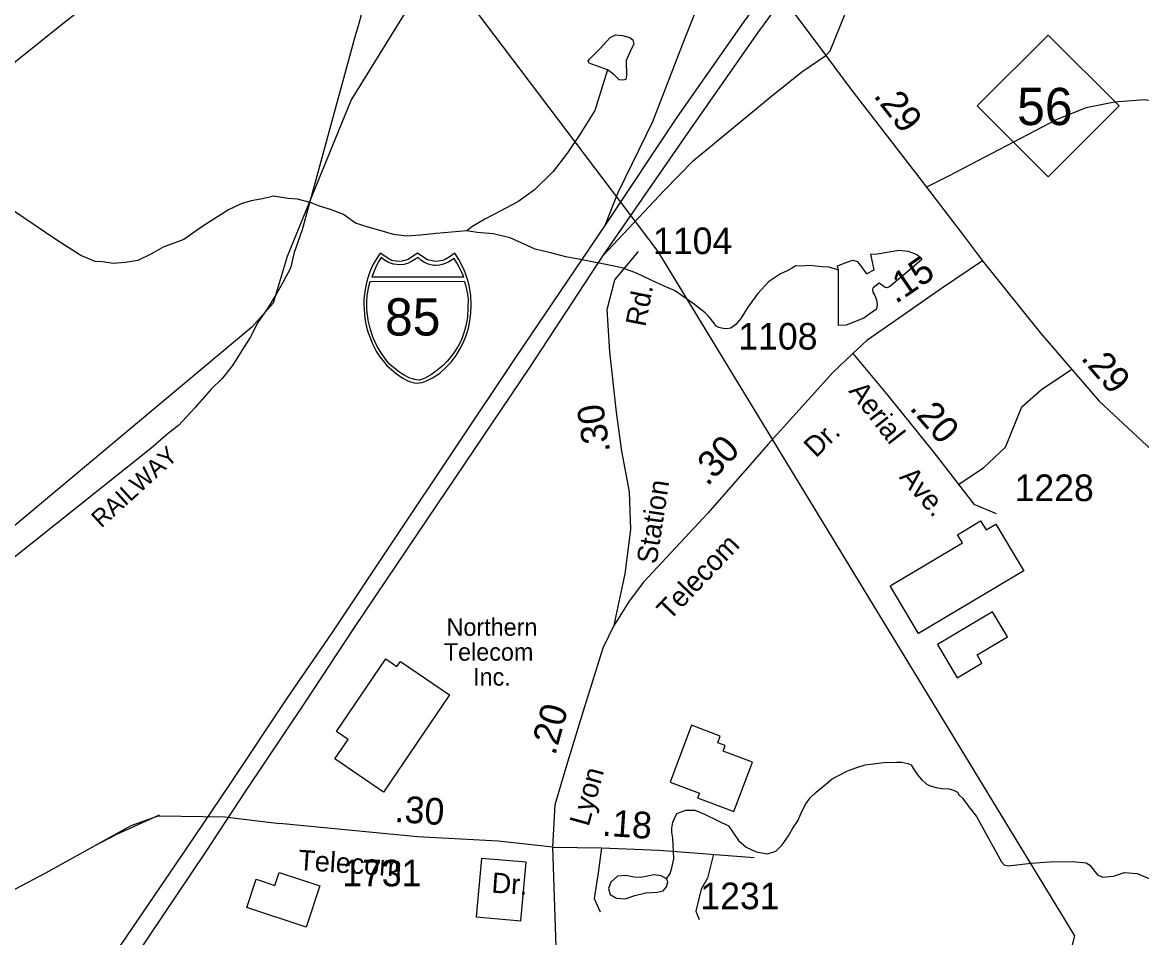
# Model space of a CAD drawing. Extents: x 2056842 to 2160602, y 826753 to 1016856.
# Drawn here: x 2077674 to 2082930, y 868296 to 872595 of the extents above; entities that cross this region are included whole.
import ezdxf

# ---------------------------------------------------------------- set-up
doc = ezdxf.new("R2010")
doc.units = 0
for name, color, linetype in [('Exist Boundary Land Use Reservation Military US Department of Defense', 7, 'Continuous'), ('Exist Cultural Manufacturing Building Label', 7, 'Continuous'), ('Exist Cultural Warehouse Building Footprint', 7, 'Continuous'), ('Exist Hydrographic Creek Single Shore', 7, 'Continuous'), ('Exist Hydrographic Misc Water Feature', 7, 'Continuous'), ('Exist Railroad Mainline', 7, 'Continuous'), ('Exist Railroad Mainline Label', 7, 'Continuous'), ('Exist Road Non-System Type 51', 7, 'Continuous'), ('Exist Road Primary Interstate Divided Center Attributed', 7, 'Continuous'), ('Exist Road Primary Interstate Ramp 1 Lane Attributed', 7, 'Continuous'), ('Exist Road Primary Interstate Shield CELL', 7, 'Continuous'), ('Exist Road Primary Interstate Shield Number Label', 7, 'Continuous'), ('Exist Road Primary NC Attributed', 7, 'Continuous'), ('Exist Road Primary NC Service Mileage Hundredths English Label', 7, 'Continuous'), ('Exist Road Primary NC Shield CELL', 7, 'Continuous'), ('Exist Road Primary NC Shield Number Label', 7, 'Continuous'), ('Exist Road Secondary Mileage Hundredths English Label', 7, 'Continuous'), ('Exist Road Secondary Type 51 Attributed', 7, 'Continuous'), ('Exist Road Secondary Type 51 Label', 7, 'Continuous'), ('Exist Road Secondary Type 51 Number Label', 7, 'Continuous'), ('Exist Utilities Electrical Transmission Line', 7, 'Continuous')]:
    doc.layers.add(name, color=color, linetype=linetype)

msp = doc.modelspace()

# ---------------------------------------------------------------- linework, layer by layer
at = {"layer": 'Exist Boundary Land Use Reservation Military US Department of Defense'}
msp.add_lwpolyline([(2079729.3, 873057.2), (2079217.9, 872231.6), (2078917.6, 871495.8), (2078852.5, 871275.5), (2078751.7, 871162.9), (2076995.4, 869694.7), (2075448.8, 868458.6), (2072205.6, 865914.9), (2069683.3, 863910.7), (2068119, 862645.9), (2067327.2, 862021.6)], dxfattribs=at)
at = {"layer": 'Exist Cultural Warehouse Building Footprint'}
for points in [[(2081749.5, 869947.8), (2082088.7, 870149.8), (2082065.6, 870188.5), (2082174.4, 870253.3), (2082199.7, 870210.8), (2082246.2, 870238.5), (2082369.5, 870031.6), (2082376.9, 870019.1), (2081882.5, 869724.6)], [(2082230, 869826.6), (2081971.6, 869673.1), (2082064.3, 869517), (2082180.4, 869586), (2082157.4, 869624.7), (2082299.7, 869709.2)], [(2079680.8, 869436), (2079369.9, 868979.5), (2079141.3, 869135.2), (2079204.1, 869227.4), (2079149.4, 869264.6), (2079381.3, 869605.1), (2079433.4, 869569.6), (2079449.6, 869593.4)], [(2080816.9, 869293.3), (2080716, 869026.7), (2080853.5, 868974.6), (2080845.1, 868952.5), (2081015.3, 868888), (2081103, 869119.8), (2080965.3, 869171.9), (2080975.3, 869198.5), (2080940.3, 869211.8), (2080951.8, 869242.2)], [(2079830.1, 868668.4), (2079805.9, 868393.7), (2080015.3, 868375.2), (2080039.5, 868649.9)], [(2079006.6, 868345.2), (2078728, 868438.1), (2078772, 868570.2), (2078859.2, 868541.1), (2078879.8, 868602.9), (2079071.2, 868539.1)]]:
    msp.add_lwpolyline(points, close=True, dxfattribs=at)
at = {"layer": 'Exist Hydrographic Creek Single Shore'}
msp.add_lwpolyline([(2079761.9, 871615.5), (2079617.9, 871603.3), (2079543.9, 871595), (2079479.9, 871590.9), (2079417.8, 871598.7), (2079370, 871612.4), (2079297.6, 871632.3), (2079238, 871651.9), (2079181.8, 871691.7), (2079121.7, 871715.9), (2079073.7, 871729.6), (2079025.7, 871749.5), (2078965.5, 871765.1), (2078921.6, 871766.9), (2078853.3, 871778.8), (2078801.6, 871766.4), (2078749.3, 871756.5), (2078701.6, 871742.2), (2078641.5, 871714), (2078590, 871682), (2078521.7, 871637.7), (2078431.9, 871575.3), (2078336.1, 871539.1), (2078280.4, 871507), (2078216.6, 871476.9), (2078156.7, 871466.5), (2078100.3, 871462.5), (2078052.4, 871470.2), (2078016.5, 871472), (2077948.6, 871500.2), (2077836.4, 871571.5), (2077574, 871748.9)], dxfattribs=at)
at = {"layer": 'Exist Hydrographic Misc Water Feature'}
for points in [[(2080422.4, 872371.3), (2080336.2, 872402.6), (2080331.2, 872412.6), (2080337.5, 872422.6), (2080386.2, 872470.1), (2080434.9, 872523.9), (2080459.9, 872536.4), (2080492.4, 872532.6), (2080527.4, 872523.9), (2080541.1, 872512.6), (2080546.1, 872493.9), (2080529.9, 872461.4), (2080509.9, 872415.1), (2080511.1, 872345.1), (2080507.4, 872326.3), (2080494.9, 872322.6), (2080476.1, 872325.1), (2080452.4, 872350.1), (2080422.4, 872371.3)], [(2080422.4, 872371.3), (2080362.3, 872181.4), (2080292.3, 872067.4), (2080234.5, 871981.3), (2080167.1, 871895), (2080079.3, 871808.9), (2080001.4, 871752.5), (2079917.5, 871708.4), (2079845.7, 871669.7), (2079785.7, 871633.9), (2079761.9, 871615.5)], [(2081506.3, 871431.4), (2081462.2, 871445), (2081430.2, 871447), (2081370.3, 871452.8), (2081334.4, 871450.5), (2081306.3, 871450.7), (2081290.5, 871442.6), (2081266.1, 871428.5), (2081234.4, 871414.1), (2081178.8, 871376.3), (2081128.5, 871321.9), (2081080.8, 871257.7), (2081048.8, 871203.8), (2081025, 871175.7), (2081001.2, 871157.8), (2080981.3, 871155.6), (2080965.5, 871157.5), (2080945, 871161.4), (2080933.1, 871167.3), (2080921, 871183.4), (2080897, 871215.3), (2080880.8, 871231.2), (2080824.9, 871275), (2080757, 871321.1), (2080736.7, 871335), (2080688.9, 871356.5), (2080626.4, 871384.6), (2080558.1, 871416.1), (2080490.2, 871442.2), (2080422.3, 871455.8), (2080302.4, 871479.7), (2080226.3, 871493.2), (2080160.1, 871510.9), (2080082.4, 871528.8), (2079964.3, 871582.4), (2079885.9, 871602), (2079809.9, 871607.8), (2079761.9, 871615.5)], [(2081506.3, 871431.4), (2081502.4, 871451.1), (2081538.2, 871465.5), (2081574.1, 871477.5), (2081594, 871471.7), (2081606.1, 871459.7), (2081638.3, 871413.8), (2081674.2, 871431.9), (2081658, 871505.8), (2081690.2, 871507.8), (2081790.3, 871524.3), (2081833.7, 871520.2), (2081858.1, 871510.3), (2081874.1, 871504.3), (2081889.9, 871492.6), (2081898.1, 871480.4), (2081862, 871450.4), (2081746.6, 871351.9), (2081734.5, 871348.1), (2081726.5, 871350.2), (2081714.6, 871358.1), (2081698.2, 871369.9), (2081670.3, 871347.7), (2081666.4, 871341.8), (2081668.7, 871327.6), (2081676.7, 871311.8), (2081684.9, 871291.9), (2081689, 871267.7), (2081684.6, 871247.7), (2081665, 871233.7), (2081625, 871205.6), (2081543.2, 871173.4), (2081507.1, 871171.2), (2081506.9, 871175.3), (2081506.3, 871431.4)], [(2080699.8, 868572.9), (2080716, 868597.9), (2080723.5, 868624.2), (2080733.5, 868666.7), (2080728.5, 868762.8), (2080724.8, 868791), (2080724.6, 868810.9), (2080728.5, 868839.2), (2080736.3, 868855), (2080748.4, 868879.2), (2080789.7, 868894.2), (2080832.2, 868894.2), (2080877.2, 868875.5), (2080942.2, 868845.5), (2080990.9, 868821.7), (2081037.1, 868751.7), (2081073.4, 868721.7), (2081119.6, 868699.2), (2081173.3, 868689.2), (2081213.3, 868702.9), (2081242.1, 868731.7), (2081272.7, 868774.5), (2081292.4, 868810.9), (2081316.4, 868844.9), (2081334.2, 868888.9), (2081353.9, 868924.9), (2081374.4, 868953.1), (2081402.1, 868979.3), (2081437.6, 869009.2), (2081477.8, 869041.3), (2081513.4, 869061.4), (2081545.4, 869077.7), (2081587.7, 869093.6), (2081631.7, 869108), (2081719.7, 869118.2), (2081779.6, 869120.4), (2081803.8, 869120.4), (2081831.7, 869114.6), (2081847.7, 869108.5), (2081859.6, 869088.4), (2081877.6, 869060.6), (2081897.7, 869036.9), (2081917.8, 869018.8), (2081937.7, 869008.9), (2081965.8, 869001), (2081994.1, 868997.1), (2082025.9, 868995), (2082049.6, 868987.5), (2082065.8, 868979.3), (2082074, 868965.4), (2082090, 868949.2), (2082118.1, 868911.3), (2082154.4, 868865.7), (2082206.6, 868770.6), (2082272.9, 868653), (2082285.4, 868638), (2082305.4, 868633), (2082344.1, 868638), (2082411.6, 868645.5), (2082497.8, 868653), (2082605.2, 868654.3), (2082670.2, 868648), (2082686.4, 868636.8), (2082722.7, 868590.4), (2082746.4, 868580.4), (2082798.9, 868585.4), (2082850.1, 868601.7), (2082910.1, 868596.7), (2083017.1, 868552.2)], [(2080699.8, 868572.9), (2080673.5, 868586.7), (2080639.8, 868591.7), (2080609.8, 868585.4), (2080576.1, 868577.9), (2080547.3, 868580.4), (2080508.6, 868587.9), (2080468.6, 868585.4), (2080437.4, 868556.7), (2080426.1, 868526.7), (2080434.9, 868499.1), (2080463.6, 868481.6), (2080504.9, 868479.1), (2080549.8, 868494.1), (2080602.3, 868506.7), (2080656, 868510.4), (2080683.5, 868516.7), (2080699.8, 868535.4), (2080704.8, 868557.9), (2080699.8, 868572.9)]]:
    msp.add_lwpolyline(points, dxfattribs=at)
at = {"layer": 'Exist Railroad Mainline'}
msp.add_lwpolyline([(2079275.5, 872670.7), (2079253.8, 872588.8), (2079234, 872520.8), (2078988.7, 871619.9), (2078951.1, 871513.9), (2078933.4, 871439.9), (2078897.6, 871373.8), (2078869.8, 871323.6), (2078825.9, 871251.5), (2078780.1, 871185.4), (2078744.3, 871115.3), (2078704.6, 871053.1), (2078660.7, 870983), (2078612.9, 870922.8), (2078561.3, 870872.7), (2078483.4, 870784.5), (2078407.7, 870702.2), (2078359.8, 870666), (2078278.1, 870593.9), (2077141.8, 869689)], dxfattribs=at)
at = {"layer": 'Exist Road Non-System Type 51'}
for points in [[(2083433.4, 872190.3), (2083365.9, 872183.6), (2083168.3, 872196.9), (2082946, 872231.1), (2082803.5, 872219.7), (2082670.5, 872193.1), (2082531.7, 872138), (2082023.4, 871872.7), (2081920.3, 871820.3)], [(2082069.9, 870425.1), (2082188.8, 870504), (2082291.4, 870599.1), (2082367.4, 870789.2), (2082460.5, 870871), (2082601.8, 870965.8)], [(2078012.9, 868726.8), (2078185.8, 868822.1), (2078312.4, 868868.3), (2078419.7, 868866.8), (2078625.5, 868863.2), (2078881.5, 868831.6)], [(2080393.1, 868718.5), (2080377.9, 868600.6), (2080358.9, 868480.8), (2080387.4, 868418.1)], [(2080919.4, 868688.1), (2080891.9, 868574.9), (2080861.5, 868523.6), (2080836.8, 868420.9), (2080852, 868381)]]:
    msp.add_lwpolyline(points, dxfattribs=at)
at = {"layer": 'Exist Road Primary Interstate Divided Center Attributed'}
for points in [[(2081193.6, 872778.4), (2081063.9, 872599.9), (2080749.9, 872151.6), (2080408.9, 871640.4)], [(2080401.7, 871499.9), (2080812.8, 872094), (2081132.3, 872551.3), (2081247.1, 872708.7)], [(2080408.9, 871640.4), (2079989.6, 871021.1), (2079420, 870167.7), (2079124.9, 869723.1), (2078921.6, 869427.8), (2078646.2, 869015.5), (2078442, 868711.3), (2078115.4, 868230.6), (2077823.9, 867791.4), (2077457.7, 867242.3), (2077165.2, 866808.4), (2076910.6, 866425), (2076571.4, 865917.3), (2076300.6, 865519.4), (2076039.6, 865125.2), (2075874.1, 864851.5), (2075734.6, 864590.5), (2075597, 864311.4), (2075525.7, 864163.6), (2075428.7, 863906.4), (2075163.3, 863260.1), (2075015.7, 862917.9)], [(2075075.1, 862859.4), (2075282, 863328.5), (2075479.1, 863825.3), (2075552.9, 863965.8), (2075675.5, 864272.5), (2075808.4, 864570.7), (2075953.3, 864828.1), (2076122.4, 865099.9), (2076367.2, 865470.8), (2076952, 866340.3), (2077230, 866759.8), (2077527.8, 867202.7), (2077895.8, 867750), (2078063.2, 867994.8), (2078537.4, 868700.5), (2078721.8, 868983.1), (2079002.5, 869400.8), (2079231.1, 869748.3), (2079535.2, 870198.3), (2080057.9, 870974.2), (2080401.7, 871499.9)]]:
    msp.add_lwpolyline(points, dxfattribs=at)
at = {"layer": 'Exist Road Primary Interstate Ramp 1 Lane Attributed'}
for points in [[(2081446.9, 872439.8), (2081468.1, 872461.6), (2081540.8, 872642.5), (2081681.5, 873023.3), (2081731.3, 873141.8), (2081865.8, 873416.7), (2081955.1, 873562.1), (2082028.6, 873734.2)], [(2080983.6, 873037.9), (2080930.7, 872885.1), (2080781.7, 872512.6), (2080632.6, 872127.5), (2080470.1, 871794.5), (2080408.9, 871640.4)], [(2080401.7, 871499.9), (2080688.7, 871805.4), (2080825.8, 871945.7), (2081183.6, 872241.3), (2081335.2, 872362.9), (2081446.9, 872439.8)]]:
    msp.add_lwpolyline(points, dxfattribs=at)
at = {"layer": 'Exist Road Primary Interstate Shield CELL'}
for points in [[(2079530.1, 870900.2), (2079539.5, 870901.1), (2079552.3, 870903.6), (2079564.7, 870907.7), (2079578.8, 870913.9), (2079599.6, 870925.4), (2079616.4, 870935.3), (2079635.7, 870948.2), (2079661.8, 870972), (2079687.9, 870999.4), (2079710.9, 871030.4), (2079729.1, 871059.4), (2079745.2, 871092.6), (2079758.6, 871123.5), (2079769.3, 871158.8), (2079776.3, 871193.1), (2079779.9, 871228.7), (2079782.3, 871268.3), (2079779.6, 871312.9), (2079771.9, 871358.4), (2079764.6, 871386.8), (2079753.6, 871420.7), (2079744.6, 871442.4), (2079723.7, 871480.8), (2079705, 871510.4), (2079677.8, 871491.3), (2079660, 871481.8), (2079649.2, 871477), (2079638, 871474.8), (2079617.5, 871472.3), (2079604.6, 871472.9), (2079592.7, 871475.6), (2079582.5, 871477.8), (2079574.3, 871481.8), (2079530.1, 871510.4), (2079485.8, 871481.8), (2079476.5, 871477.6), (2079467, 871475.6), (2079457.9, 871473), (2079442.7, 871472.3), (2079431.1, 871472.7), (2079419.3, 871474.8), (2079409.9, 871476.8), (2079399.4, 871481.8), (2079354.3, 871510.4), (2079336.5, 871484.7), (2079322.1, 871459.3), (2079306.7, 871423.4), (2079297.2, 871395.6), (2079290.4, 871372.7), (2079282, 871330.7), (2079277.7, 871294.2), (2079277, 871268.3), (2079281.7, 871203.8), (2079288.7, 871169.5), (2079296, 871141.7), (2079319.8, 871081.6), (2079337.8, 871048), (2079353.2, 871023.9), (2079374.8, 870996.7), (2079386.5, 870983.7), (2079431.3, 870944.6), (2079461.2, 870924.1), (2079485.1, 870911.2), (2079496.3, 870906.9), (2079513.9, 870902)], [(2079359.6, 871489.7), (2079348.6, 871472.8), (2079336, 871449.9), (2079325.8, 871426.3), (2079315.5, 871400.1), (2079747, 871399.9), (2079737, 871422.4), (2079726.2, 871444.9), (2079715, 871465.5), (2079701.3, 871485.4), (2079677.1, 871470.1), (2079659.4, 871461.8), (2079645.3, 871456.9), (2079633.3, 871454.2), (2079614.7, 871452.7), (2079606.4, 871453.2), (2079580.4, 871459.1), (2079562.9, 871466.3), (2079546.2, 871477.4), (2079532.6, 871490.1), (2079498.4, 871469.4), (2079483.3, 871462.8), (2079465.8, 871458.3), (2079446.8, 871455.9), (2079417.3, 871459.1), (2079394.3, 871467.1), (2079374.4, 871477.4)], [(2079749.6, 871378.6), (2079754.2, 871366.5), (2079760.6, 871339.4), (2079763.9, 871318.6), (2079767.3, 871294.6), (2079766.1, 871253.5), (2079764.1, 871210.9), (2079760.2, 871185.7), (2079755, 871162.7), (2079747.8, 871137.3), (2079736.3, 871103.4), (2079720.4, 871074.8), (2079700.5, 871042.9), (2079679, 871015.1), (2079669.7, 871003.5), (2079652, 870984.9), (2079619.8, 870959), (2079596.3, 870941.4), (2079568.1, 870924.8), (2079553.8, 870918.4), (2079537.1, 870914.9), (2079523.4, 870915.9), (2079506.8, 870920.3), (2079493.3, 870924), (2079463.9, 870939.9), (2079440, 870955.8), (2079400.3, 870988.4), (2079378.8, 871013.6), (2079358.8, 871042.9), (2079340.9, 871073), (2079321.8, 871112.7), (2079308.4, 871152.6), (2079298.6, 871195.7), (2079292, 871248.3), (2079291.3, 871280.4), (2079293.2, 871311.2), (2079296.1, 871327.4), (2079300.1, 871347.5), (2079307.9, 871378.4)]]:
    msp.add_lwpolyline(points, close=True, dxfattribs=at)
at = {"layer": 'Exist Road Primary NC Attributed'}
for points in [[(2077218.5, 872072.4), (2077299.8, 872137), (2077872.5, 872595.3), (2078566, 873132.7), (2078891.9, 873393)], [(2081247.1, 872708.7), (2081446.9, 872439.8)], [(2081446.9, 872439.8), (2081564.6, 872281.4), (2081868.5, 871887.9), (2082098.6, 871587.5), (2082183.6, 871474.2)], [(2082183.6, 871474.2), (2082457.6, 871132.9), (2082731, 870816.1), (2083000.6, 870565.7), (2083201.5, 870381.5)]]:
    msp.add_lwpolyline(points, dxfattribs=at)
at = {"layer": 'Exist Road Primary NC Shield CELL'}
msp.add_lwpolyline([(2082158.5, 872202), (2082491.5, 872535), (2082824.5, 872202), (2082491.5, 871869)], close=True, dxfattribs=at)
at = {"layer": 'Exist Road Secondary Type 51 Attributed'}
for points in [[(2080452.6, 869763), (2080504.4, 870004.8), (2080531.2, 870213.5), (2080525.2, 870389.4), (2080489.5, 870580.2), (2080464.9, 870764.3), (2080433.6, 871047.6), (2080420.9, 871246.6), (2080456.7, 871385.2), (2080566.9, 871519.3)], [(2082183.6, 871474.2), (2081990.6, 871345.3), (2081756.8, 871182.8), (2081640.6, 871100.8), (2081573.5, 871039.7)], [(2081573.5, 871039.7), (2081480.4, 870951), (2081176.6, 870614.1), (2080892.8, 870289.9), (2080591.1, 869965.7), (2080524.1, 869876.3), (2080452.6, 869763)], [(2081573.5, 871039.7), (2081738.1, 870842.2), (2081954.1, 870573.9), (2082142.6, 870331.7), (2082246.9, 870288.4)], [(2080165.1, 868721), (2080177, 868920.8), (2080235.1, 869122), (2080316.3, 869382.1), (2080401.2, 869657.9), (2080452.6, 869763)], [(2074618.1, 867871.2), (2074680.7, 867907), (2074972.2, 868146.9), (2075052.8, 868203.3), (2075081.8, 868215), (2075123.2, 868219), (2075210.2, 868198.4), (2075268.3, 868198.4), (2075717.5, 868279.6), (2075967.7, 868310.9), (2076380.8, 868337.8), (2077102, 868384.7), (2077341.9, 868414.5), (2077498.3, 868450.3), (2077785, 868600.1), (2078012.9, 868726.8), (2078118.3, 868782.3), (2078317.9, 868872.6)], [(2080165.1, 868721), (2079908.5, 868749.7), (2079530.1, 868769.1), (2078881.5, 868831.6)], [(2080272.7, 867443.2), (2080238.5, 867578.8), (2080194.5, 867821), (2080183.3, 868206.4), (2080165.1, 868721)], [(2080165.1, 868721), (2080393.1, 868718.5), (2080664.8, 868707.1), (2081110.9, 868672.8)]]:
    msp.add_lwpolyline(points, dxfattribs=at)
at = {"layer": 'Exist Utilities Electrical Transmission Line'}
msp.add_lwpolyline([(2079289.6, 845905.8), (2079948.4, 849305.4), (2079483.2, 855866.2), (2080101, 858353.8), (2081583.8, 864201.8), (2082616, 868304.1), (2080660.7, 871519), (2079505, 873046.5), (2077150, 875999.6), (2076168.7, 877076.1), (2079417.8, 882691.3), (2077477.1, 888146.6), (2075950.7, 892161.6), (2073748.3, 895216.6), (2070106.7, 900031.7)], dxfattribs=at)

# ---------------------------------------------------------------- texts
at = {"layer": 'Exist Cultural Manufacturing Building Label'}
for s, p in [('Northern', (2079666.2, 869713.9)), ('Telecom', (2079653.4, 869597)), ('Inc.', (2079790.9, 869479.8))]:
    msp.add_text(s, height=82.02, dxfattribs=at).set_placement(p)
at = {"layer": 'Exist Railroad Mainline Label'}
msp.add_text('RAILWAY', height=82.02, rotation=42.3389, dxfattribs=at).set_placement((2078044.5, 870217.1))
at = {"layer": 'Exist Road Primary Interstate Shield Number Label'}
msp.add_text('85', height=175, dxfattribs=at).set_placement((2079377.2, 871124))
at = {"layer": 'Exist Road Primary NC Service Mileage Hundredths English Label'}
for rotation, p in [(307.6755, (2081668.2, 872249.5)), (310.7924, (2082641, 871016.1))]:
    msp.add_text('.29', height=125, rotation=rotation, dxfattribs=at).set_placement(p)
at = {"layer": 'Exist Road Primary NC Shield Number Label'}
msp.add_text('56', height=175, dxfattribs=at).set_placement((2082345.6, 872112.3))
at = {"layer": 'Exist Road Secondary Mileage Hundredths English Label'}
for s, rotation, p in [('.15', 34.3027, (2081776.3, 871270.7)), ('.20', 311.0653, (2081836.8, 870781.2)), ('.30', 98.5638, (2080435.1, 870579.1)), ('.30', 46.4853, (2080890.8, 870413.2)), ('.20', 74.4593, (2080176.2, 869148.5)), ('.30', 356.174, (2079419.9, 868839.8)), ('.18', 356.174, (2080394.6, 868775.3))]:
    msp.add_text(s, height=125, rotation=rotation, dxfattribs=at).set_placement(p)
at = {"layer": 'Exist Road Secondary Type 51 Label'}
for s, rotation, p in [('Rd.', 78.91, (2080599.3, 871161.7)), ('Aerial', 307.9399, (2081551.3, 870862.3)), ('Dr.', 43.94, (2081400.2, 870546.1)), ('Ave.', 311.0653, (2081788.5, 870456.8)), ('Station', 81.28, (2080652.4, 870047.4)), ('Telecom', 46.4853, (2080713.6, 869781.4)), ('Lyon', 74.4921, (2080333.3, 868814.6)), ('Telecom', 356.174, (2078967.5, 868614.4)), ('Dr.', 356.174, (2079875.4, 868507.8))]:
    msp.add_text(s, height=95, rotation=rotation, dxfattribs=at).set_placement(p)
at = {"layer": 'Exist Road Secondary Type 51 Number Label'}
for s, p in [('1104', (2080635.9, 871506.2)), ('1108', (2081036.3, 871057.9)), ('1228', (2082333.7, 870346.4)), ('1731', (2079176.3, 868537)), ('1231', (2080858.1, 868429.7))]:
    msp.add_text(s, height=125, dxfattribs=at).set_placement(p)

doc.saveas('drawing.dxf')
